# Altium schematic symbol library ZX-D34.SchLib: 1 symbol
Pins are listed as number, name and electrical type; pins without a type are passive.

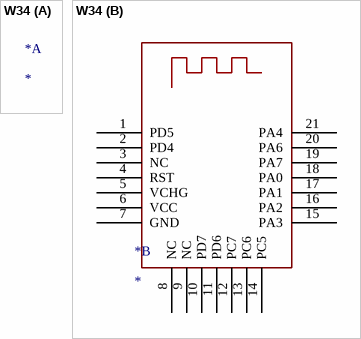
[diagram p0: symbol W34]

## W34
designator *
part B pins: 1 PD5 "AT选择引脚", 2 PD4 "AT选择引脚", 3 NC "AT选择引脚", 4 RST "AT选择引脚", 5 VCHG "AT选择引脚", 6 VCC "AT选择引脚", 7 GND "AT选择引脚", 8 NC "AT选择引脚", 9 NC "AT选择引脚", 10 PD7 "AT选择引脚", 11 PD6 "AT选择引脚", 12 PC7 "AT选择引脚", 13 PC6 "AT选择引脚", 14 PC5 "AT选择引脚", 15 PA3 "AT选择引脚", 16 PA2 "AT选择引脚", 17 PA1 "AT选择引脚", 18 PA0 "AT选择引脚", 19 PA7 "AT选择引脚", 20 PA6 "AT选择引脚", 21 PA4 "AT选择引脚"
